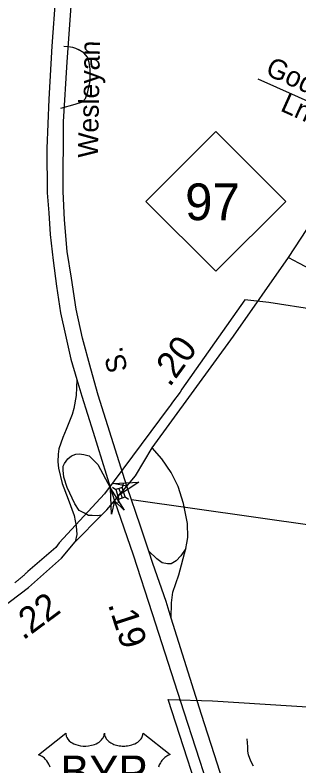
# Model space of a CAD drawing. Extents: x 2220236 to 2384410, y 720751 to 894131.
# Drawn here: x 2345738 to 2347089, y 787885 to 791463 of the extents above; entities that cross this region are included whole.
import ezdxf

# ---------------------------------------------------------------- set-up
doc = ezdxf.new("R2010")
doc.units = 0
doc.layers.add('Default', color=7, linetype='Continuous')

msp = doc.modelspace()

# ---------------------------------------------------------------- linework, layer by layer
at = {"layer": 'Default'}
for p, q in [((2346892.9, 791158.9), (2347400.6, 790933.2)), ((2345955.6, 791019.3), (2346024.1, 791038.8)), ((2346201.6, 789213.1), (2346216.8, 789202)), ((2346231.8, 789206.9), (2346246.7, 789161.9)), ((2346252.4, 789229.9), (2346246.8, 789211.9)), ((2346261.7, 789166.8), (2346276.9, 789155.7)), ((2346232, 789157), (2346226.4, 789139)), ((2346291.3, 789154.2), (2347226.6, 789021.6))]:
    msp.add_line(p, q, dxfattribs=at)
for points in [[(2346268.9, 789218.5), (2346133.2, 789652), (2346098.6, 789777.6), (2346058.8, 789923.7), (2346028.9, 790061.5), (2346005.7, 790209.2), (2345985.8, 790337), (2345972.5, 790488.1), (2345965.9, 790622.5), (2345967.5, 790954.5), (2345985.8, 791240), (2346009.2, 791573.6), (2346049, 792133), (2346077.2, 792554.6), (2346133.6, 793313.2), (2346173.4, 793932.3)], [(2346098.8, 793892.5), (2346057.3, 793331.4), (2346002.5, 792561.2), (2345972.7, 792134.7), (2345964.4, 792031.7), (2345912.9, 791314.7), (2345897.8, 791062.4), (2345889.6, 790826.7), (2345891.2, 790615.9), (2345897.8, 790521.3), (2345904.5, 790416.7), (2345919.4, 790293.9), (2345934.4, 790171), (2345954.3, 790044.9), (2345977.5, 789937), (2346002.4, 789824.1), (2346031.3, 789726.3)], [(2346389.9, 789400.7), (2346777.2, 789932.6), (2347039.5, 790308.1), (2347155.8, 790487.8), (2347257.4, 790659.3), (2347379.8, 790881.4), (2347400.6, 790933.2), (2347502.1, 791133.1), (2347613.8, 791376.7)], [(2345969.8, 791314.2), (2345991.7, 791312.9), (2346011.3, 791310.2), (2346024.5, 791306), (2346037.3, 791298.6)], [(2346024.1, 791038.8), (2346058.4, 791049), (2346072.1, 791065.2), (2346083.8, 791097.2), (2346095.1, 791149.3), (2346094.4, 791205.3), (2346090.1, 791237.2), (2346081.9, 791263), (2346065.6, 791283), (2346037.3, 791298.6)], [(2347039.5, 790308.1), (2347085.9, 790281.9), (2347119.5, 790264.4), (2347151.8, 790250.9), (2347181.4, 790241.5), (2347212.3, 790232.1), (2347255.3, 790221.3), (2347344.1, 790206.5), (2347427.5, 790191.7), (2347607.7, 790164.8), (2347778.5, 790136.5), (2347845.8, 790128.4)], [(2347169.2, 790058.2), (2346944.5, 790093.9), (2346831.2, 790106.6), (2346811.8, 790079.1), (2346531, 789680.3), (2346523, 789666), (2346487.5, 789618.4), (2346474.2, 789599.4), (2346473.5, 789598.4), (2346472.5, 789597.6), (2346471, 789596.1), (2346163.5, 789182.4), (2345946.8, 788948.4), (2345932, 788926.6), (2345799.2, 788811.3), (2345797.5, 788809.6), (2345795.5, 788807.9), (2345793.8, 788806.3), (2345791.8, 788804.6), (2345790, 788803), (2345788, 788801.3), (2345786.2, 788799.7), (2345784.2, 788798), (2345782.5, 788796.4), (2345780.5, 788794.8), (2345778.8, 788793.1), (2345776.8, 788791.4), (2345774.8, 788789.8), (2345773, 788788.2), (2345771, 788786.5), (2345769.2, 788784.9), (2345767.2, 788783.2), (2345765.5, 788781.6), (2345763.5, 788780), (2345761.5, 788778.4), (2345759.8, 788776.8), (2345757.8, 788775.1), (2345756, 788773.5), (2345754, 788771.9), (2345752, 788770.2), (2345750.2, 788768.6), (2345748.2, 788767.1), (2345746.2, 788765.4), (2345744.5, 788763.8), (2345742.5, 788762.2), (2345740.5, 788760.6), (2345738.8, 788759), (2345736.8, 788757.4)], [(2347169.2, 790058.2), (2346944.5, 790093.9), (2346831.2, 790106.6), (2346811.8, 790079.1), (2346531, 789680.3), (2346523, 789666), (2346487.5, 789618.4), (2346474.2, 789599.4), (2346473.5, 789598.4), (2346472.5, 789597.6), (2346471, 789596.1), (2346163.5, 789182.4), (2345946.8, 788948.4), (2345932, 788926.6), (2345799.2, 788811.3), (2345797.5, 788809.6), (2345795.5, 788807.9), (2345793.8, 788806.3), (2345791.8, 788804.6), (2345790, 788803), (2345788, 788801.3), (2345786.2, 788799.7), (2345784.2, 788798), (2345782.5, 788796.4), (2345780.5, 788794.8), (2345778.8, 788793.1), (2345776.8, 788791.4), (2345774.8, 788789.8), (2345773, 788788.2), (2345771, 788786.5), (2345769.2, 788784.9), (2345767.2, 788783.2), (2345765.5, 788781.6), (2345763.5, 788780), (2345761.5, 788778.4), (2345759.8, 788776.8), (2345757.8, 788775.1), (2345756, 788773.5), (2345754, 788771.9), (2345752, 788770.2), (2345750.2, 788768.6), (2345748.2, 788767.1), (2345746.2, 788765.4), (2345744.5, 788763.8), (2345742.5, 788762.2), (2345740.5, 788760.6), (2345738.8, 788759), (2345736.8, 788757.4)], [(2346031.3, 789726.3), (2346028, 789650.7), (2346016.7, 789588.5), (2346009.1, 789560.2), (2345981.2, 789487.6), (2345965.5, 789450.8), (2345946.5, 789396), (2345942.1, 789371.5), (2345941, 789334.6), (2345944.3, 789304.4), (2345961.1, 789230.7), (2345990.1, 789157), (2346019.1, 789078.8), (2346028.7, 789027.3), (2346031.1, 788987.2), (2346023.5, 788953.3)], [(2346031.3, 789726.3), (2346054.6, 789647.6), (2346108.8, 789475), (2346191.7, 789208.5)], [(2346268.9, 789218.5), (2346310.9, 789268.2), (2346389.9, 789400.7)], [(2346549.5, 788921.5), (2346555.1, 788947.2), (2346559.1, 788973.6), (2346558.4, 789039.6), (2346539.9, 789135.2), (2346514.4, 789217), (2346479.8, 789284), (2346435.7, 789348.2), (2346389.9, 789400.7)], [(2346148.6, 789079.9), (2346129.6, 789076.7), (2346104, 789078), (2346087.2, 789078.8), (2346068.2, 789088.8), (2346042.6, 789102.2), (2346022.5, 789133.5), (2345985.6, 789211.7), (2345970, 789260.9), (2345966.6, 789294.4), (2345967.2, 789312.8), (2345972.2, 789326.8), (2345989.5, 789348.6), (2346006.3, 789362), (2346026.4, 789370.9), (2346042, 789373.1), (2346064.3, 789369.8), (2346090.1, 789362.2), (2346131.2, 789321), (2346191.7, 789208.5)], [(2346191.7, 789208.5), (2346210.2, 789148.9)], [(2346210.2, 789148.9), (2346268.9, 789218.5)], [(2346373.6, 788908.9), (2346333.9, 789027.9), (2346268.9, 789218.5)], [(2346148.6, 789079.9), (2346161.5, 789093.1), (2346174, 789105.8), (2346210.2, 789148.9)], [(2346210.2, 789148.9), (2346300.2, 788891.8), (2346389.8, 788611.3), (2346540.8, 788143.2), (2346651.9, 787799.6), (2346774.7, 787411.2), (2346947.6, 786869.7), (2347015.3, 786660.5), (2347069.4, 786501.8), (2347364.1, 785590.9)], [(2346023.5, 788953.3), (2346148.6, 789079.9)], [(2345313.3, 788416.6), (2345422.2, 788471.8), (2345621.9, 788600.6), (2345802.3, 788734.6), (2345958.5, 788874.4), (2346023.5, 788953.3)], [(2346549.5, 788921.5), (2346526.1, 788885.8), (2346504.6, 788863.1), (2346480.7, 788848.7), (2346463.6, 788847.8), (2346438.1, 788852.8), (2346412.2, 788871.6), (2346373.6, 788908.9)], [(2346481.2, 788589.6), (2346482.6, 788662.4), (2346488.9, 788712.5), (2346517.2, 788796.4), (2346549.5, 788921.5)], [(2346481.2, 788589.6), (2346456.1, 788669.4), (2346393.1, 788850.3), (2346373.6, 788908.9)], [(2347439.5, 785590.9), (2347132.2, 786550.5), (2347015.3, 786913.2), (2346837.7, 787462.6), (2346701.7, 787894.2), (2346625.4, 788129.9), (2346481.2, 788589.6)], [(2346668.2, 787578.6), (2346465.5, 788201.5), (2346677, 788194.9), (2347579.2, 788138.8), (2347756, 787579)], [(2346668.2, 787578.6), (2346465.5, 788201.5), (2346677, 788194.9), (2347579.2, 788138.8), (2347756, 787579)], [(2345905.2, 787879), (2345902, 787887.5), (2345899.1, 787893.7), (2345894.2, 787902.1), (2345888.7, 787910), (2345883.1, 787916.3), (2345877.4, 787922), (2345871.9, 787926.3), (2345866.7, 787930), (2345860.2, 787934), (2345853.9, 787937.1), (2345849.9, 787938.7), (2345978.5, 788041.1), (2345978.8, 788035.8), (2345980.1, 788029.5), (2345981.1, 788026.2), (2345984.1, 788020), (2345988.9, 788012.6), (2345995.7, 788005.4), (2346003.4, 787999.1), (2346008.6, 787995.8), (2346017.3, 787991), (2346027.3, 787986.9), (2346038.4, 787983.7), (2346049.7, 787981.4), (2346062.1, 787980), (2346074.3, 787979.8), (2346087.5, 787980.8), (2346102.1, 787983.6), (2346108.8, 787985.3), (2346116.4, 787987.9), (2346123.3, 787990.8), (2346131, 787994.9), (2346137.2, 787998.9), (2346142, 788002.4), (2346148.8, 788008.9), (2346154.3, 788015.7), (2346156.5, 788019.5), (2346158.5, 788023.1), (2346161.2, 788030.9), (2346162, 788034.3), (2346162.5, 788041.4), (2346163, 788035.4), (2346163.6, 788031.7), (2346164.6, 788028.1), (2346166.1, 788024.2), (2346168.8, 788018.7), (2346171.8, 788014.1), (2346177.6, 788007.4), (2346181.1, 788004), (2346184.4, 788001.4), (2346193.1, 787995.4), (2346203.4, 787990.2), (2346208.4, 787988), (2346213.5, 787986.2), (2346220.1, 787984.2), (2346226.8, 787982.6), (2346233.5, 787981.5), (2346240.3, 787980.5), (2346247.3, 787980), (2346253, 787979.8), (2346260, 787979.9), (2346266.5, 787980.3), (2346273.1, 787981), (2346280.4, 787982.2), (2346286.2, 787983.5), (2346294, 787985.6), (2346301, 787988.1), (2346307.1, 787990.7), (2346315.1, 787994.9), (2346321.5, 787998.9), (2346326.2, 788002.8), (2346331.9, 788007.9), (2346337.2, 788014.1), (2346340.3, 788018.6), (2346342.5, 788023.2), (2346344.6, 788028.1), (2346345.8, 788033.2), (2346346.4, 788037.7), (2346346.5, 788041.5), (2346475.1, 787939.1), (2346472.1, 787937.9), (2346465.1, 787934.5), (2346459.6, 787931.2), (2346450.7, 787925), (2346446.9, 787921.6), (2346443.1, 787918), (2346439.6, 787914.2), (2346436.6, 787910.7), (2346432.8, 787905.5), (2346429.5, 787900.3), (2346426.2, 787894.6), (2346423.8, 787889.7), (2346419.9, 787879.3)], [(2346872.2, 787883.7), (2346861, 787905), (2346854.3, 787920.6), (2346848.8, 787937.4), (2346845.4, 787955.2), (2346845.4, 787976.5), (2346842.1, 788014.4)]]:
    msp.add_lwpolyline(points, dxfattribs=at)
for points in [[(2346359.7, 790575.4), (2346692.7, 790908.4), (2347025.7, 790575.4), (2346692.7, 790242.4)], [(2346205.1, 789230.5), (2346326.8, 789237.7), (2346225, 789170.6), (2346268.9, 789218.5)], [(2346197.3, 789085.2), (2346191.9, 789207), (2346257.4, 789104.2), (2346210.2, 789148.9)], [(2346216.8, 789202), (2346231.7, 789156.9), (2346261.7, 789166.8), (2346246.8, 789211.9)]]:
    msp.add_lwpolyline(points, close=True, dxfattribs=at)

# ---------------------------------------------------------------- texts
for s, height, rotation, p in [('Wesleyan', 95, 88.9142, (2346131.5, 790782.4)), ('Godwin', 95, 335.8061, (2346924, 791180.9)), ('Ln.', 95, 335.8061, (2346995.3, 791008.9)), ('.20', 125, 53.9357, (2346473.3, 789686.6)), ('S.', 95, 104.6874, (2346275.1, 789772.7)), ('.22', 125, 36.6046, (2345776.2, 788481.6)), ('.19', 125, 287.8771, (2346178.6, 788655.3))]:
    msp.add_text(s, height=height, rotation=rotation, dxfattribs=at).set_placement(p)
for s, height, p in [('97', 175, (2346546.8, 790485.7)), ('BYP', 155, (2345953.2, 787779.8))]:
    msp.add_text(s, height=height, dxfattribs=at).set_placement(p)

doc.saveas('drawing.dxf')
